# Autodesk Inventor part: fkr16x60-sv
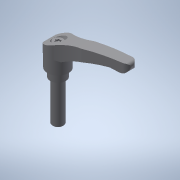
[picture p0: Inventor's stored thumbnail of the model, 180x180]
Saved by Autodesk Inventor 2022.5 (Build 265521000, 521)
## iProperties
Created: 2017-09
Part Number: fkr16x60-sv
Material: 一般
Document SubType Name: Modeling
Designer: imaocorp
Density: 1 g/cm^3
Appearance: 既定
Author: imaocorp
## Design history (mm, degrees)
node "fkr16x60-sv.x_t1"
node "fkr16x60-sv"
node "Base1"
